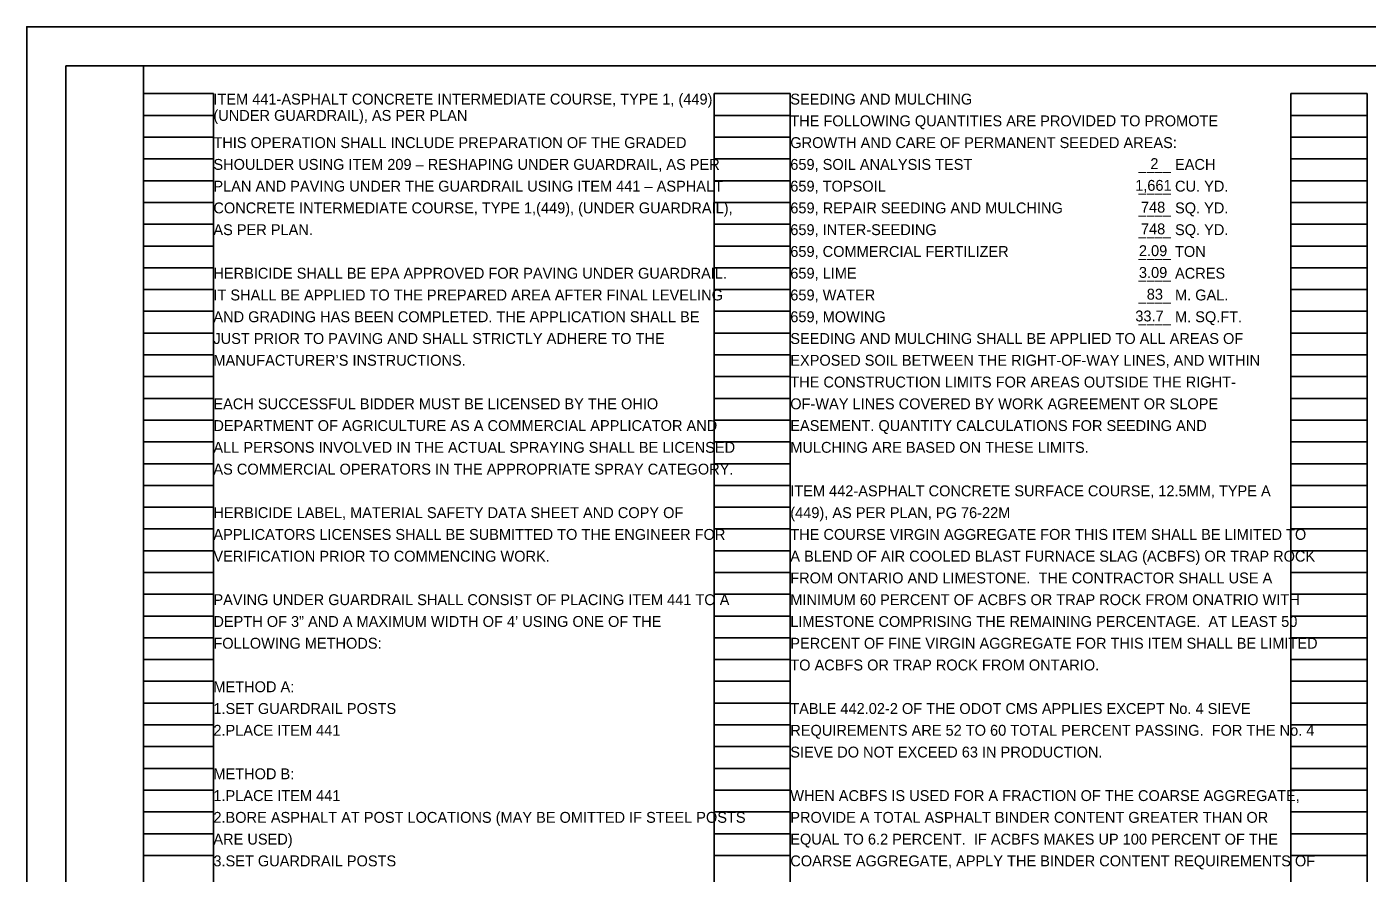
# Model space of a CAD drawing. Extents: x 0 to 74, y -27.6 to 51.8.
# Drawn here: x 0 to 17.24, y 11.11 to 22 of the extents above; entities that cross this region are included whole.
import ezdxf

# ---------------------------------------------------------------- set-up
doc = ezdxf.new("R2010")
doc.units = 0
for name, color, linetype in [('Level 1', 7, 'Continuous'), ('Level 2', 7, 'Continuous'), ('Level 3', 7, 'Continuous'), ('Level 4', 7, 'Continuous')]:
    doc.layers.add(name, color=color, linetype=linetype)

msp = doc.modelspace()

# ---------------------------------------------------------------- linework, layer by layer
at = {"layer": 'Level 1'}
msp.add_lwpolyline([(0, 0), (34, 0), (34, 22), (0, 22)], close=True, dxfattribs=at)
at = {"layer": 'Level 2'}
for points in [[(0.5, 21.5), (1.5, 21.5), (1.5, 0.5), (0.5, 0.5)], [(1.5, 21.5), (33.5, 21.5), (33.5, 0.5), (1.5, 0.5)]]:
    msp.add_lwpolyline(points, close=True, dxfattribs=at)
at = {"layer": 'Level 3'}
for p, q in [((1.5, 0.98), (1.5, 21.14)), ((1.5, 21.14), (2.4, 21.14)), ((2.4, 0.98), (2.4, 21.14)), ((8.84, 0.98), (8.84, 21.14)), ((8.84, 21.14), (9.82, 21.14)), ((9.82, 0.98), (9.82, 21.14)), ((16.26, 0.98), (16.26, 21.14)), ((16.26, 21.14), (17.24, 21.14)), ((17.24, 0.98), (17.24, 21.14)), ((1.5, 20.86), (2.4, 20.86)), ((8.84, 20.86), (9.82, 20.86)), ((16.26, 20.86), (17.24, 20.86)), ((1.5, 20.58), (2.4, 20.58)), ((8.84, 20.58), (9.82, 20.58)), ((16.26, 20.58), (17.24, 20.58)), ((1.5, 20.3), (2.4, 20.3)), ((8.84, 20.3), (9.82, 20.3)), ((16.26, 20.3), (17.24, 20.3)), ((1.5, 20.02), (2.4, 20.02)), ((8.84, 20.02), (9.82, 20.02)), ((16.26, 20.02), (17.24, 20.02)), ((1.5, 19.74), (2.4, 19.74)), ((8.84, 19.74), (9.82, 19.74)), ((16.26, 19.74), (17.24, 19.74)), ((1.5, 19.46), (2.4, 19.46)), ((8.84, 19.46), (9.82, 19.46)), ((16.26, 19.46), (17.24, 19.46)), ((1.5, 19.18), (2.4, 19.18)), ((8.84, 19.18), (9.82, 19.18)), ((16.26, 19.18), (17.24, 19.18)), ((1.5, 18.9), (2.4, 18.9)), ((8.84, 18.9), (9.82, 18.9)), ((16.26, 18.9), (17.24, 18.9)), ((1.5, 18.62), (2.4, 18.62)), ((8.84, 18.62), (9.82, 18.62)), ((16.26, 18.62), (17.24, 18.62)), ((1.5, 18.34), (2.4, 18.34)), ((8.84, 18.34), (9.82, 18.34)), ((16.26, 18.34), (17.24, 18.34)), ((1.5, 18.06), (2.4, 18.06)), ((8.84, 18.06), (9.82, 18.06)), ((16.26, 18.06), (17.24, 18.06)), ((1.5, 17.78), (2.4, 17.78)), ((8.84, 17.78), (9.82, 17.78)), ((16.26, 17.78), (17.24, 17.78)), ((1.5, 17.5), (2.4, 17.5)), ((8.84, 17.5), (9.82, 17.5)), ((16.26, 17.5), (17.24, 17.5)), ((1.5, 17.22), (2.4, 17.22)), ((8.84, 17.22), (9.82, 17.22)), ((16.26, 17.22), (17.24, 17.22)), ((1.5, 16.94), (2.4, 16.94)), ((8.84, 16.94), (9.82, 16.94)), ((16.26, 16.94), (17.24, 16.94)), ((1.5, 16.66), (2.4, 16.66)), ((8.84, 16.66), (9.82, 16.66)), ((16.26, 16.66), (17.24, 16.66)), ((1.5, 16.38), (2.4, 16.38)), ((8.84, 16.38), (9.82, 16.38)), ((16.26, 16.38), (17.24, 16.38)), ((1.5, 16.1), (2.4, 16.1)), ((8.84, 16.1), (9.82, 16.1)), ((16.26, 16.1), (17.24, 16.1)), ((1.5, 15.82), (2.4, 15.82)), ((8.84, 15.82), (9.82, 15.82)), ((16.26, 15.82), (17.24, 15.82)), ((1.5, 15.54), (2.4, 15.54)), ((8.84, 15.54), (9.82, 15.54)), ((16.26, 15.54), (17.24, 15.54)), ((1.5, 15.26), (2.4, 15.26)), ((8.84, 15.26), (9.82, 15.26)), ((16.26, 15.26), (17.24, 15.26)), ((1.5, 14.98), (2.4, 14.98)), ((8.84, 14.98), (9.82, 14.98)), ((16.26, 14.98), (17.24, 14.98)), ((1.5, 14.7), (2.4, 14.7)), ((8.84, 14.7), (9.82, 14.7)), ((16.26, 14.7), (17.24, 14.7)), ((1.5, 14.42), (2.4, 14.42)), ((8.84, 14.42), (9.82, 14.42)), ((16.26, 14.42), (17.24, 14.42)), ((1.5, 14.14), (2.4, 14.14)), ((8.84, 14.14), (9.82, 14.14)), ((16.26, 14.14), (17.24, 14.14)), ((1.5, 13.86), (2.4, 13.86)), ((8.84, 13.86), (9.82, 13.86)), ((16.26, 13.86), (17.24, 13.86)), ((1.5, 13.58), (2.4, 13.58)), ((8.84, 13.58), (9.82, 13.58)), ((16.26, 13.58), (17.24, 13.58)), ((1.5, 13.3), (2.4, 13.3)), ((8.84, 13.3), (9.82, 13.3)), ((16.26, 13.3), (17.24, 13.3)), ((1.5, 13.02), (2.4, 13.02)), ((8.84, 13.02), (9.82, 13.02)), ((16.26, 13.02), (17.24, 13.02)), ((1.5, 12.74), (2.4, 12.74)), ((8.84, 12.74), (9.82, 12.74)), ((16.26, 12.74), (17.24, 12.74)), ((1.5, 12.46), (2.4, 12.46)), ((8.84, 12.46), (9.82, 12.46)), ((16.26, 12.46), (17.24, 12.46)), ((1.5, 12.18), (2.4, 12.18)), ((8.84, 12.18), (9.82, 12.18)), ((16.26, 12.18), (17.24, 12.18)), ((1.5, 11.9), (2.4, 11.9)), ((8.84, 11.9), (9.82, 11.9)), ((16.26, 11.9), (17.24, 11.9)), ((1.5, 11.62), (2.4, 11.62)), ((8.84, 11.62), (9.82, 11.62)), ((16.26, 11.62), (17.24, 11.62)), ((1.5, 11.34), (2.4, 11.34)), ((8.84, 11.34), (9.82, 11.34)), ((16.26, 11.34), (17.24, 11.34))]:
    msp.add_line(p, q, dxfattribs=at)

# ---------------------------------------------------------------- texts
at = {"layer": 'Level 4'}
for s, p in [('ITEM 441-ASPHALT CONCRETE INTERMEDIATE COURSE, TYPE 1, (449)', (2.4, 21)), ('SEEDING AND MULCHING', (9.82, 21)), ('(UNDER GUARDRAIL), AS PER PLAN', (2.4, 20.79)), ('THE FOLLOWING QUANTITIES ARE PROVIDED TO PROMOTE', (9.82, 20.72)), ('THIS OPERATION SHALL INCLUDE PREPARATION OF THE GRADED ', (2.4, 20.44)), ('GROWTH AND CARE OF PERMANENT SEEDED AREAS:', (9.82, 20.44)), ('SHOULDER USING ITEM 209 – RESHAPING UNDER GUARDRAIL, AS PER ', (2.4, 20.16)), ('659, SOIL ANALYSIS TEST         ', (9.82, 20.16)), ('____ EACH', (14.3, 20.16)), ('2', (14.451, 20.17)), ('PLAN AND PAVING UNDER THE GUARDRAIL USING ITEM 441 – ASPHALT ', (2.4, 19.88)), ('659, TOPSOIL                       ', (9.82, 19.88)), ('1,661', (14.256, 19.89)), ('____ CU. YD.', (14.3, 19.88)), ('CONCRETE INTERMEDIATE COURSE, TYPE 1,(449), (UNDER GUARDRAIL), ', (2.4, 19.6)), ('659, REPAIR SEEDING AND MULCHING   ', (9.82, 19.6)), ('____ SQ. YD.', (14.3, 19.6)), ('748', (14.33, 19.61)), ('AS PER PLAN.  ', (2.4, 19.32)), ('659, INTER-SEEDING                 ', (9.82, 19.32)), ('____ SQ. YD.', (14.3, 19.32)), ('748', (14.33, 19.33)), ('659, COMMERCIAL FERTILIZER         ', (9.82, 19.04)), ('____ TON', (14.3, 19.04)), ('2.09', (14.304, 19.05)), ('HERBICIDE SHALL BE EPA APPROVED FOR PAVING UNDER GUARDRAIL. ', (2.4, 18.76)), ('659, LIME                          ', (9.82, 18.76)), ('____ ACRES', (14.3, 18.76)), ('3.09', (14.304, 18.77)), ('IT SHALL BE APPLIED TO THE PREPARED AREA AFTER FINAL LEVELING ', (2.4, 18.48)), ('659, WATER                         ', (9.82, 18.48)), ('____ M. GAL.', (14.3, 18.48)), ('83', (14.405, 18.49)), ('AND GRADING HAS BEEN COMPLETED. THE APPLICATION SHALL BE ', (2.4, 18.2)), ('659, MOWING                        ', (9.82, 18.2)), ('33.7', (14.258, 18.21)), ('____ M. SQ.FT.', (14.3, 18.2)), ('JUST PRIOR TO PAVING AND SHALL STRICTLY ADHERE TO THE ', (2.4, 17.92)), ('SEEDING AND MULCHING SHALL BE APPLIED TO ALL AREAS OF', (9.82, 17.92)), ('MANUFACTURER’S INSTRUCTIONS.  ', (2.4, 17.64)), ('EXPOSED SOIL BETWEEN THE RIGHT-OF-WAY LINES, AND WITHIN', (9.82, 17.64)), ('THE CONSTRUCTION LIMITS FOR AREAS OUTSIDE THE RIGHT-', (9.82, 17.36)), ('EACH SUCCESSFUL BIDDER MUST BE LICENSED BY THE OHIO ', (2.4, 17.08)), ('OF-WAY LINES COVERED BY WORK AGREEMENT OR SLOPE', (9.82, 17.08)), ('DEPARTMENT OF AGRICULTURE AS A COMMERCIAL APPLICATOR AND ', (2.4, 16.8)), ('EASEMENT. QUANTITY CALCULATIONS FOR SEEDING AND', (9.82, 16.8)), ('ALL PERSONS INVOLVED IN THE ACTUAL SPRAYING SHALL BE LICENSED ', (2.4, 16.52)), ('MULCHING ARE BASED ON THESE LIMITS.', (9.82, 16.52)), ('AS COMMERCIAL OPERATORS IN THE APPROPRIATE SPRAY CATEGORY.  ', (2.4, 16.24)), ('ITEM 442-ASPHALT CONCRETE SURFACE COURSE, 12.5MM, TYPE A ', (9.82, 15.96)), ('HERBICIDE LABEL, MATERIAL SAFETY DATA SHEET AND COPY OF ', (2.4, 15.68)), ('(449), AS PER PLAN, PG 76-22M', (9.82, 15.68)), ('APPLICATORS LICENSES SHALL BE SUBMITTED TO THE ENGINEER FOR ', (2.4, 15.4)), ('THE COURSE VIRGIN AGGREGATE FOR THIS ITEM SHALL BE LIMITED TO ', (9.82, 15.4)), ('VERIFICATION PRIOR TO COMMENCING WORK.  ', (2.4, 15.12)), ('A BLEND OF AIR COOLED BLAST FURNACE SLAG (ACBFS) OR TRAP ROCK ', (9.82, 15.12)), ('FROM ONTARIO AND LIMESTONE.  THE CONTRACTOR SHALL USE A ', (9.82, 14.84)), ('PAVING UNDER GUARDRAIL SHALL CONSIST OF PLACING ITEM 441 TO A ', (2.4, 14.56)), ('MINIMUM 60 PERCENT OF ACBFS OR TRAP ROCK FROM ONATRIO WITH ', (9.82, 14.56)), ('DEPTH OF 3” AND A MAXIMUM WIDTH OF 4’ USING ONE OF THE ', (2.4, 14.28)), ('LIMESTONE COMPRISING THE REMAINING PERCENTAGE.  AT LEAST 50 ', (9.82, 14.28)), ('FOLLOWING METHODS:  ', (2.4, 14)), ('PERCENT OF FINE VIRGIN AGGREGATE FOR THIS ITEM SHALL BE LIMITED ', (9.82, 14)), ('TO ACBFS OR TRAP ROCK FROM ONTARIO. ', (9.82, 13.72)), ('METHOD A: ', (2.4, 13.44)), ('1.SET GUARDRAIL POSTS ', (2.4, 13.16)), ('TABLE 442.02-2 OF THE ODOT CMS APPLIES EXCEPT No. 4 SIEVE ', (9.82, 13.16)), ('2.PLACE ITEM 441  ', (2.4, 12.88)), ('REQUIREMENTS ARE 52 TO 60 TOTAL PERCENT PASSING.  FOR THE No. 4 ', (9.82, 12.88)), ('SIEVE DO NOT EXCEED 63 IN PRODUCTION.', (9.82, 12.6)), ('METHOD B: ', (2.4, 12.32)), ('1.PLACE ITEM 441 ', (2.4, 12.04)), ('WHEN ACBFS IS USED FOR A FRACTION OF THE COARSE AGGREGATE, ', (9.82, 12.04)), ('2.BORE ASPHALT AT POST LOCATIONS (MAY BE OMITTED IF STEEL POSTS ', (2.4, 11.76)), ('PROVIDE A TOTAL ASPHALT BINDER CONTENT GREATER THAN OR ', (9.82, 11.76)), ('ARE USED) ', (2.4, 11.48)), ('EQUAL TO 6.2 PERCENT.  IF ACBFS MAKES UP 100 PERCENT OF THE ', (9.82, 11.48)), ('3.SET GUARDRAIL POSTS ', (2.4, 11.2)), ('COARSE AGGREGATE, APPLY THE BINDER CONTENT REQUIREMENTS OF ', (9.82, 11.2))]:
    msp.add_text(s, height=0.14, dxfattribs=at).set_placement(p)

doc.saveas('drawing.dxf')
